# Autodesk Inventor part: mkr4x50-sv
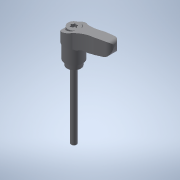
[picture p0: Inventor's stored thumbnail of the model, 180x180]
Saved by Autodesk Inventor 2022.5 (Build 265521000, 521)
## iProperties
Created: 2017-09
Part Number: mkr4x50-sv
Material: 一般
Document SubType Name: Modeling
Designer: imaocorp
Density: 1 g/cm^3
Appearance: 既定
Author: imaocorp
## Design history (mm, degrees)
node "mkr4x50-sv.x_t1"
node "mkr4x50-sv"
node "Base1"
